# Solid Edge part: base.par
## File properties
Title: Base
Author: Deepak Maini
Template: Normal.par
Last saved by: Robert a Rhodes jr
Revision: 15
Application: Solid Edge
Material: aluminum
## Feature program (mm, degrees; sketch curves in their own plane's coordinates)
sketch for "unnamed Protrusion 1" plane through (0, 0, 0) normal (0, 0, 1) x-axis (1, 0, 0)
  line (-85, 25) -> (-85, -25)
  arc centre (-80, -25) radius 5 from (-85, -25) to (-80, -30) ccw
  line (-80, -30) -> (80, -30)
  arc centre (80, -25) radius 5 from (85, -25) to (80, -30) cw
  line (85, -25) -> (85, 25)
  arc centre (80, 25) radius 5 from (80, 30) to (85, 25) cw
  line (80, 30) -> (-80, 30)
  arc centre (-80, 25) radius 5 from (-85, 25) to (-80, 30) cw
extrude "unnamed Protrusion 1" add finite 20 along +normal
sketch for "unnamed Protrusion 2" plane through (5, -12, 10) normal (0, -1, 0) x-axis (1, 0, 0)
  line (-50, 10) -> (-50, 50)
  arc centre (15, 50) radius 65 from (-50, 50) to (-20, 104.7723) cw
  line (-20, 104.7723) -> (-20, 144.4119)
  arc centre (-17, 144.4119) radius 3 from (-20, 144.4119) to (-17, 147.4119) cw
  line (-17, 147.4119) -> (37, 147.4119)
  arc centre (37, 144.4119) radius 3 from (37, 147.4119) to (40, 144.4119) cw
  line (40, 144.4119) -> (40, 75.4119)
  line (40, 75.4119) -> (-12.5101, 75.4119)
  line (-12.5101, 35) -> (-12.5101, 75.4119)
  line (9.4899, 10) -> (-12.5101, 35)
  line (32, 35) -> (9.4899, 10)
  line (40, 35) -> (32, 35)
  line (40, 35) -> (40, 10)
extrude "unnamed Protrusion 2" add
sketch for "unnamed Cutout 1" plane through (5, -12, 88.5) normal (0, -1, 0) x-axis (1, 0, 0)
  line (-20.5101, -68.5) -> (-20.5101, 4.1219)
  arc centre (-25.5101, 4.1219) radius 5 from (-29.3611, 7.3109) to (-20.5101, 4.1219) cw
  arc centre (13, -27.7681) radius 55 from (-42, -27.7681) to (-29.3611, 7.3109) cw
  line (-42, -68.5) -> (-42, -27.7681)
  line (-42, -68.5) -> (-20.5101, -68.5)
extrude "unnamed Cutout 1" cut finite 10 along -normal
sketch for "unnamed Cutout 2" plane through (5, 0, 0) normal (0, 0, -1) x-axis (1, 0, 0)
  line (-10.5101, 1) -> (-10.5101, -19)
  line (-10.5101, -19) -> (29.4899, -19)
  line (29.4899, -19) -> (29.4899, 1)
  line (29.4899, 1) -> (-10.5101, 1)
  dimension (linear) = 10.5101
extrude "unnamed Cutout 2" cut finite 147 along -normal
sketch for "unnamed Protrusion 3" plane through (25, 9, 157.4119) normal (0, 0, 1) x-axis (1, 0, 0)
  circle centre (-10, 0) radius 15
  dimension (linear) = 10
extrude "unnamed Protrusion 3" add finite 18 along +normal
sketch for "unnamed Hole 1" plane through (25, 9, 175.4119) normal (0, 0, 1) x-axis (1, 0, 0)
  hole centre (-10, 0) bore radius 10
hole "unnamed Hole 1" finite
sketch for "unnamed Hole 2" plane through (45, 9, 119.9119) normal (1, 0, 0) x-axis (0, 1, 0)
  hole centre (1, 20.5) bore radius 4
  dimension (linear) = 1
hole "unnamed Hole 2" through
mirror "unnamed Mirror 1" of "unnamed Cutout 1" about plane through (5, 9, 88.7059) normal (0, -1, 0)
extrude "unnamed Cutout 3" cut finite 10
fillet "unnamed Round 1"
sketch for "unnamed Hole 3" plane through (0, 0, 20) normal (0, 0, 1) x-axis (1, 0, 0)
  hole centre (70, 0) bore radius 6.5
hole "unnamed Hole 3" through
sketch for "unnamed Hole 4" plane through (0, 0, 20) normal (0, 0, 1) x-axis (1, 0, 0)
  hole centre (-70, 0) bore radius 6.5
  dimension (linear) = 70
  dimension (linear) = 70
hole "unnamed Hole 4" through
pattern "unnamed Pattern 1" of "unnamed Hole 3", "unnamed Hole 4"
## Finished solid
Body 1: solid body, 60 faces, 161 edges, 98 vertices.
  Faces by surface: plane 36, cylinder 23, torus 1
  Edges by curve: line 111, circle 50
Bounding box of the edges (mm; curved faces can reach further): 170.000 x 60.000 x 175.412, from (-85, -30, 0) to (85, 30, 175.4119).
Cylindrical faces by radius (mm): R3 x8, R4 x2, R5 x6, R6.5 x2, R10 x1, R15 x1, R55 x2, R65 x1
Toroidal faces (ring radius, tube radius in mm): R18 r3 x1
Planar faces by outward normal: +x 8, +y 4, +z 5, -x 7, -y 6, -z 4, oblique 2
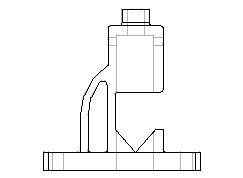
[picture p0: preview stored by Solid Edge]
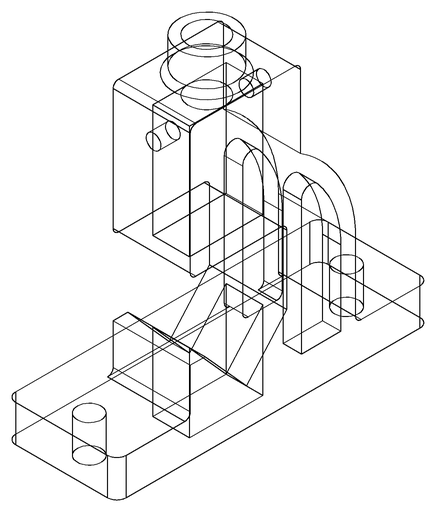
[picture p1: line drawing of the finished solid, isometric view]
